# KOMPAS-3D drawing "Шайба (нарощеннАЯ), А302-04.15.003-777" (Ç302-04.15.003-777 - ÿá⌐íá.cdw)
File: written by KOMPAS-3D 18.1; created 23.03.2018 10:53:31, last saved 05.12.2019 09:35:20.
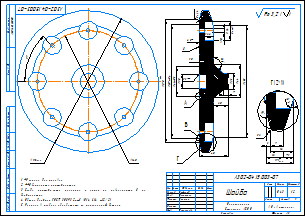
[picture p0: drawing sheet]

Sheet 1: A3, landscape

Document properties: Автор: Милов; Параметр неуказанной шероховатости: Ra 3,2; Полное имя файла: ..\3Д ПВХ\А302-01.15.003 - Шайба.m3d; Масса: 0.432773; Организация: Милов

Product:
- Part/product: (unnamed)  | designation 7
- Part/product: Шайба (нарощеннАЯ)  | designation А302-04.15.003-777
    Материал: Полипропилен  ГОСТ 26996-86 (density 900 kg/m3)
    Масса: 0.432773
    Раздел спецификации: Детали
    Форматы листов документа: A4
    source file: А302-04.15.003-777 - Шайба.cdw
- Part/product: Шайба  | designation А302-02.15.003
    Материал: Полипропилен  ГОСТ 26996-86 (density 900 kg/m3)
    Масса: 0.251914
    Раздел спецификации: Детали
    Форматы листов документа: A4
- Part/product: Шайба  | designation А302-01.15.003
    Масса: 0.292092
    Раздел спецификации: Детали
    Форматы листов документа: A4
- Part/product: Шайба  | designation А302-03.15.003
    Материал: Полипропилен  ГОСТ 26996-86 (density 900 kg/m3)
    Масса: 0.28231
    Раздел спецификации: Детали
    Форматы листов документа: A4
    source file: ..\Чертежи Полипропилен\А302-03.15.003 - Шайба.cdw
- Part/product: Шайба  | designation А302-05.15.003
    Материал: Поливинилхлорид (density 0 kg/m3)
    Раздел спецификации: Детали
    Форматы листов документа: A4
    source file: ..\Чертежи ПВХ\А302-02.15.003 - Шайба.cdw, ..\Чертежи Полипропилен\А302-03.15.003 - Шайба.cdw, А302-04.15.003 - Шайба.cdw
  - Body: Тело 10
      Масса: 0.249827
- Part/product: Шайба  | designation А302-04.15.003
    Материал: Полипропилен  ГОСТ 26996-86 (density 900 kg/m3)
    Масса: 0.247573
    Раздел спецификации: Детали
    Форматы листов документа: A4

Title block, sheet 1: Наименование: Шайба; designation: А302-04.15.003 - 07; Материал: Полипропилен / Стержень  200; Масса: 0,43; scale: 1:2; Количество листов документа: 1; organisation: АО «Астерион»; Форматы листов документа: A3; stored path: \\192.168.87.28\Konstructor_doc\Мембранные насосы\Мембранный электропривод\А302-00.00.000 - ASTRA-302 (МЭ200)\Чертежи\А302-00.15.003 - Шайба.cdw; Разработал: Лифлянд; Проверил: Борисенко; Т. контр.: Лучихин; Утвердил: Григорьева

Views: Вид 1, Местный разрез 1, Спереди, Проекционный вид 2, Выносной элемент 3, Выносной элемент 4, Выносной элемент 5, Выносной элемент 6, Выносной элемент А, Выносной элемент, Выносной элемент Б, Выносной элемент В, Выносной элемент Г
Referenced files in D:\Мембранные насосы\Мембранный электропривод\А302-00.00.000 - ASTRA-302 (МЭ200)\3Д ПВХ\: А302-01.15.003 - Шайба.m3d
Referenced files in Z:\Мембранные насосы\Мембранный электропривод\А302-00.00.000 - ASTRA-302 (МЭ200)\3Д\: А302-00.15.003 - Шайба.m3d
Referenced files in Z:\Мембранные насосы\Мембранный электропривод\А302-00.00.000 - ASTRA-302 (МЭ200)\3Д ПВХ\: А302-01.15.003 - Шайба.m3d
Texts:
  Ra 1,6
  Зона контакта с мембраной
  поверхность глянцевая
  Ra 0,80
  Ra 3,2
  Ra 3,2 ( )
  Шайба (нарощеннАЯ)
Dimensions and other numbers on the sheet: 6,5; 46; 23; 20; 3; 10; 41±0,3; 157±0,4; 170; 5; 40; 12,6; 130; 155; 7; 26; 8 отв.; 196; 140; 1±0,1; 2; 0,5; 19,1; 7,1; 12; 19 7'; 9; 16; 1:2; 0,43; 777

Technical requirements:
  *Размеры для справок.
  **Обеспечить инструментом.
  Следы инструмента, царапины и риски на поверхности  Д  не
  допускаются.
  Общие допуски ГОСТ 30893.2-mK (H14, h14,  t2/2).
  Размеры в скобках обработать по сопрягаемой детали.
